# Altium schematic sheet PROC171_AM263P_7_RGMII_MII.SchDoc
size 431 x 279 mm; Date: Not shown in title block; ApprovedBy: Not shown in title block; CheckedBy: Not shown in title block; Author: Not shown in title block; CompanyName: Not shown in title block; Engineer: Not shown in title block; Organization: Not shown in title block; Address1: Not shown in title block; Address2: Not shown in title block; Address3: Not shown in title block; Address4: Not shown in title block; DocumentNumber: 11; Revision: Use project parameter SCH_Rev; SheetNumber: 11; SheetTotal: 26; PageSetup: Record=PageOptions¦CenterHorizontal=True¦CenterVertical=True¦PrintScale=1.00¦XCorrection=1.00¦YCorrection=1.00¦PrintKind=0¦BorderSize=5000000¦LeftOffset=0¦BottomOffset=0¦Orientation=2¦PaperLength=1000¦PaperWidth=1000¦Scale=100¦PaperSource=15¦PrintQuality=600¦MediaType=1¦DitherType=10¦PaperKind=Letter¦PrintScaleMode=1
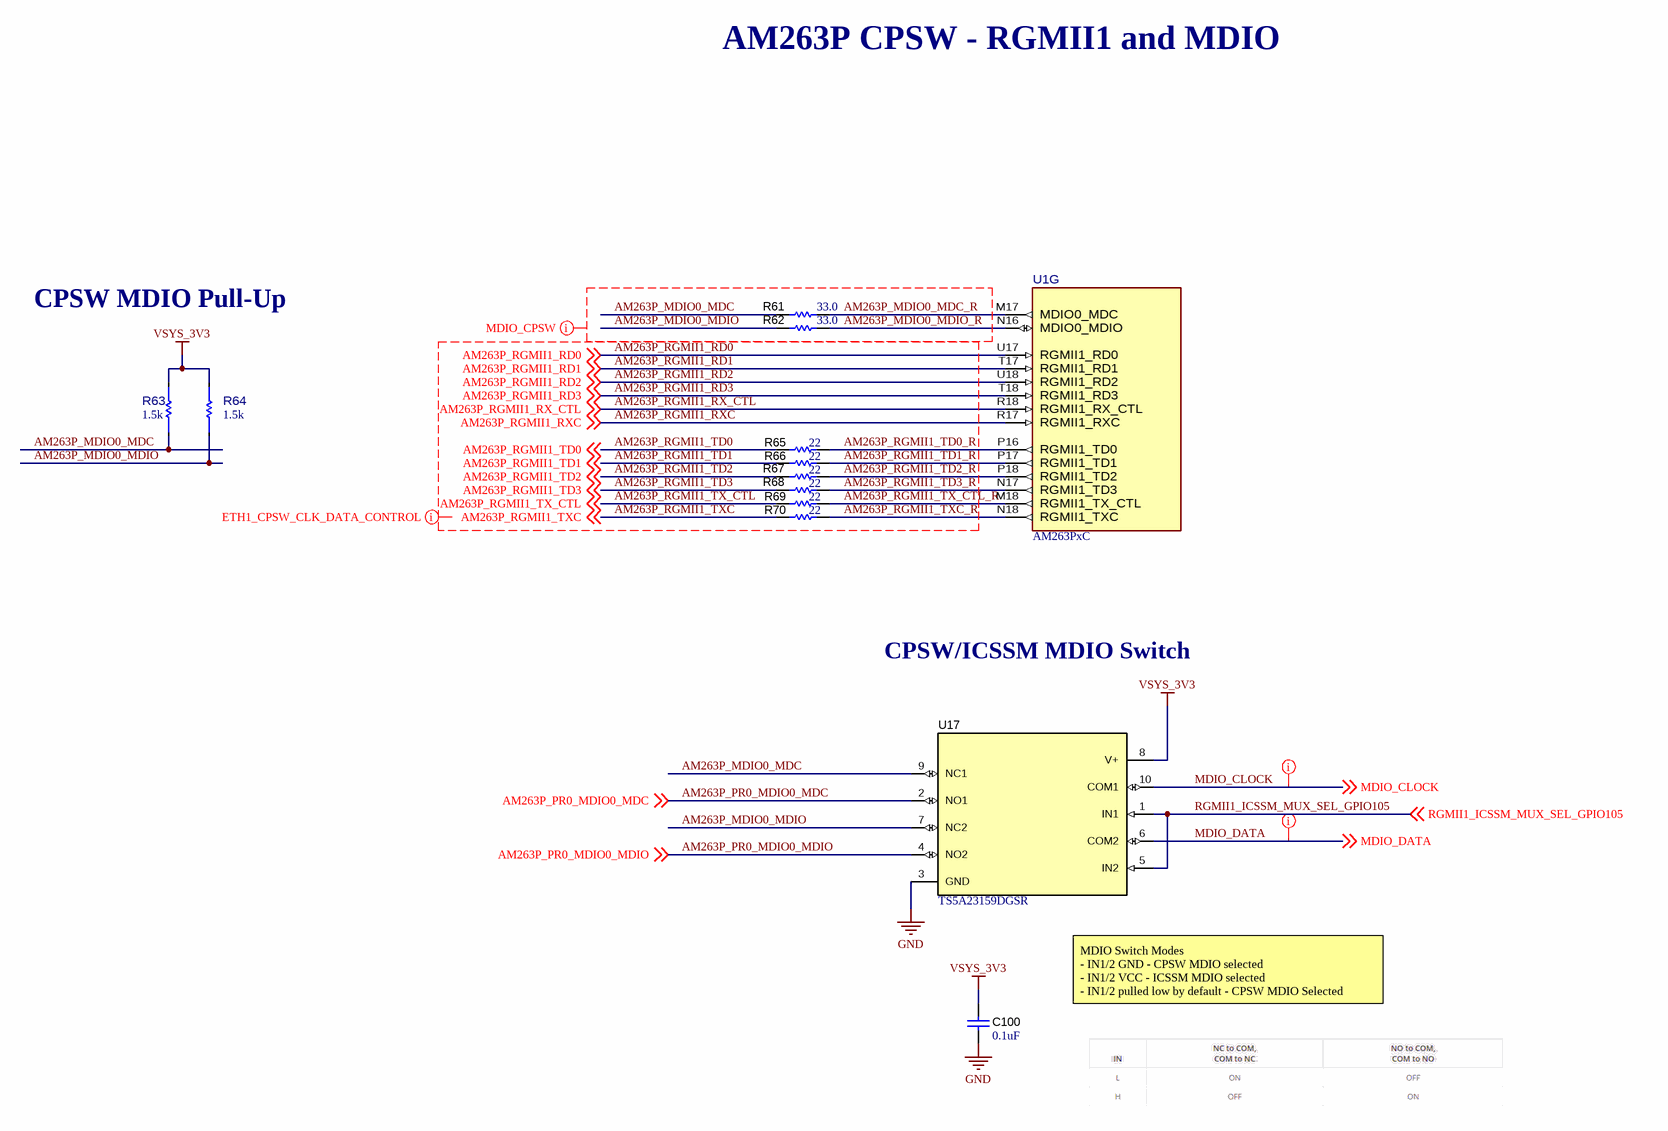
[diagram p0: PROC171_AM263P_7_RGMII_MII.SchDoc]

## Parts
C100  ValueDisplayed: 0.1uF  [0402]  (hidden comment: GRM155R71E104KE14D)
R61  ValueDisplayed: 33.0  [0402L]  (hidden comment: ERJ-2RKF33R0X)
R62  ValueDisplayed: 33.0  [0402L]  (hidden comment: ERJ-2RKF33R0X)
R63  value 1.5k  [FP-ERJ-2GEJ152X_0402-MFG]  (hidden comment: ERJ-2GEJ152X)
R64  value 1.5k  [FP-ERJ-2GEJ152X_0402-MFG]  (hidden comment: ERJ-2GEJ152X)
R65  ValueDisplayed: 22  [0402]  (hidden comment: CRCW040222R0JNED)
R66  ValueDisplayed: 22  [0402]  (hidden comment: CRCW040222R0JNED)
R67  ValueDisplayed: 22  [0402]  (hidden comment: CRCW040222R0JNED)
R68  ValueDisplayed: 22  [0402]  (hidden comment: CRCW040222R0JNED)
R69  ValueDisplayed: 22  [0402]  (hidden comment: CRCW040222R0JNED)
R70  ValueDisplayed: 22  [0402]  (hidden comment: CRCW040222R0JNED)
U1  AM263PxC  [ZCZ0324A-MFG]  (part G of 13)
U17  TS5A23159DGSR  [DGS0010A_N]

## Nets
GND: C100.1 U17.3(GND)
VSYS_3V3: C100.2 R63.2 R64.2 U17.8(V+)
AM263P_MDIO0_MDC: R61.1 R63.1 U17.9(NC1)
AM263P_MDIO0_MDC_R: R61.2 U1.M17(MDIO0_MDC)
AM263P_MDIO0_MDIO: R62.1 R64.1 U17.7(NC2)
AM263P_MDIO0_MDIO_R: R62.2 U1.N16(MDIO0_MDIO)
AM263P_PR0_MDIO0_MDC: U17.2(NO1) ; off-sheet AM263P_PR0_MDIO0_MDC
AM263P_PR0_MDIO0_MDIO: U17.4(NO2) ; off-sheet AM263P_PR0_MDIO0_MDIO
AM263P_RGMII1_RD0: U1.U17(RGMII1_RD0) ; off-sheet AM263P_RGMII1_RD0
AM263P_RGMII1_RD1: U1.T17(RGMII1_RD1) ; off-sheet AM263P_RGMII1_RD1
AM263P_RGMII1_RD2: U1.U18(RGMII1_RD2) ; off-sheet AM263P_RGMII1_RD2
AM263P_RGMII1_RD3: U1.T18(RGMII1_RD3) ; off-sheet AM263P_RGMII1_RD3
AM263P_RGMII1_RX_CTL: U1.R18(RGMII1_RX_CTL) ; off-sheet AM263P_RGMII1_RX_CTL
AM263P_RGMII1_RXC: U1.R17(RGMII1_RXC) ; off-sheet AM263P_RGMII1_RXC
AM263P_RGMII1_TD0: R65.1 ; off-sheet AM263P_RGMII1_TD0
AM263P_RGMII1_TD0_R: R65.2 U1.P16(RGMII1_TD0)
AM263P_RGMII1_TD1: R66.1 ; off-sheet AM263P_RGMII1_TD1
AM263P_RGMII1_TD1_R: R66.2 U1.P17(RGMII1_TD1)
AM263P_RGMII1_TD2: R67.1 ; off-sheet AM263P_RGMII1_TD2
AM263P_RGMII1_TD2_R: R67.2 U1.P18(RGMII1_TD2)
AM263P_RGMII1_TD3: R68.1 ; off-sheet AM263P_RGMII1_TD3
AM263P_RGMII1_TD3_R: R68.2 U1.N17(RGMII1_TD3)
AM263P_RGMII1_TX_CTL: R69.1 ; off-sheet AM263P_RGMII1_TX_CTL
AM263P_RGMII1_TX_CTL_R: R69.2 U1.M18(RGMII1_TX_CTL)
AM263P_RGMII1_TXC: R70.1 ; off-sheet AM263P_RGMII1_TXC
AM263P_RGMII1_TXC_R: R70.2 U1.N18(RGMII1_TXC)
MDIO_CLOCK: U17.10(COM1) ; off-sheet MDIO_CLOCK
MDIO_DATA: U17.6(COM2) ; off-sheet MDIO_DATA
RGMII1_ICSSM_MUX_SEL_GPIO105: U17.1(IN1) U17.5(IN2) ; off-sheet RGMII1_ICSSM_MUX_SEL_GPIO105

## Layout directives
mark named ETH1_CPSW_CLK_DATA_CONTROL: AM263P_RGMII1_RD0, AM263P_RGMII1_RD1, AM263P_RGMII1_RD2, AM263P_RGMII1_RD3, AM263P_RGMII1_RX_CTL, AM263P_RGMII1_RXC, AM263P_RGMII1_TD0, AM263P_RGMII1_TD0_R, AM263P_RGMII1_TD1, AM263P_RGMII1_TD1_R, AM263P_RGMII1_TD2, AM263P_RGMII1_TD2_R, AM263P_RGMII1_TD3, AM263P_RGMII1_TD3_R, AM263P_RGMII1_TX_CTL, AM263P_RGMII1_TX_CTL_R, AM263P_RGMII1_TXC, AM263P_RGMII1_TXC_R
mark named MDIO_CPSW: AM263P_MDIO0_MDC, AM263P_MDIO0_MDC_R, AM263P_MDIO0_MDIO, AM263P_MDIO0_MDIO_R
mark named MDIO: MDIO_CLOCK, MDIO_DATA

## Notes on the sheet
- AM263P CPSW - RGMII1 and MDIO
- CPSW MDIO Pull-Up
- CPSW/ICSSM MDIO Switch
- MDIO Switch Modes
  - IN1/2 GND - CPSW MDIO selected
  - IN1/2 VCC - ICSSM MDIO selected
  - IN1/2 pulled low by default - CPSW MDIO Selected

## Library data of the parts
C100 = CMP-0006659-2: CAP, CERM, 0.1 uF, 25 V, +/- 10%, X7R, 0402; Manufacturer: MuRata; TaMin_C: -55°C; Polarized: N; SizeAreaWB_mm2: 3; U/M: EA; Value: 0.1uF; TaMax_C: 125°C; SizeZ_mm: 0.6; SizeX_mm: 1; SizeY_mm: 0.5; Value2: 25V; Cap_F: 100nF; AEC Category: Q200; Value1: Unknown
R61 R62 = CMP-0026696-1: RES, 33.0, 1%, 0.1 W, 0402; Manufacturer: Panasonic; Power_W: 100mW; TempCo: 100 ppm/C; Value_Code: 33R0; U/M: EA; Value: 33.0; Res_ohm: 33; SizeX_mm: 1; SizeY_mm: 0.5; SizeZ_mm: 0.6; Value2: 0.1W; VDC_V: 50V; AEC Category: Q200
R63 R64 = CMP-0042990-1: Res Thick Film 0402 1.5K Ohm 5% 1/10W ±200ppm/°C Molded SMD Punched Carrier T/R; Manufacturer: Panasonic; AEC Grade: Grade 0; AEC Qualified: Yes; Power_W: 100mW; SizeZ_mm: 0.4mm; VDC_V: 50V; Category 5A00970A6D5C81C7: Uncategorized; Category 5C6A91606D4187Ad: Resistors; Category 7542B8484461Ae85: Passive Components; Category Cd01000Bfc2916C6: Single Components
R65-R70 = CMP-0026880-3: RES, 22, 5%, 0.063 W, AEC-Q200 Grade 0, 0402; Manufacturer: Vishay-Dale; Power_W: 63mW; TempCo: 200 ppm/C; Value_Code: 22R0; Value: 22; EIA_Code: E24; SizeX_mm: 1; SizeY_mm: 0.5; SizeZ_mm: 0.6; Value2: 0.063W; AEC Qualified: Y; VDC_V: 50V; AEC Category: Q200; AEC Grade: 0
U1 = CMP-0001698-2: Sitara™ Microcontroller; Manufacturer: Texas Instruments; SizeZ_mm: 1.4mm; Core Architecture: ARM Cortex-R5F; Data Bus Width: 32bits; Frequency_Fixed: 200MHz; Interface: I2C,SPI,UART,CAN,LIN,Ethernet,Other; Max Supply Voltage: 3.465V; Memory Size: 2MBytes; Memory Type: RAM; Min Supply Voltage: 1.14V; Number Of Cores: 1; Number Of I/Os: 140; Number Of I2C Channels: 4; Number Of Spi Channels: 5; Number Of Uart Channels: 6; Standoff Height: 0.35mm; AEC Category: Q200; CompType: IC
U17 = CMP-0067419-2: 2-Channel, 2:1 Analog Switch with Low On-State Resistance (1ohm) and Powered Off Protection, DGS0010A (VSSOP-10); Alternate PartNumber: TS5A23159DGST; Alternate Manufacturer: Texas Instruments; Green_Lifecycle: Active; SizeAreaWB_mm2: 23.6; Green_REACh: Passed; SizeZ_mm: 1.1; SizeX_mm: 4.9; SizeY_mm: 3.0; SizeArea_mm2: 14.7; CompType: IC; AEC Category: Q200; AEC Qualified: N; Rating: Catalog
